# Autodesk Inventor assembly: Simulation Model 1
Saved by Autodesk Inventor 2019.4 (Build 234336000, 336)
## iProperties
Created: 2020-06
Part Number: Simulation Model 1
Document SubType Name: Assembly
Designer: Administrator
Title: Simulation Model 1
Author: Administrator
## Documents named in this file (4)
- c:\worker\convert-fusion-r04\tmp\job-1\14\output\files\60eb285b-71d1-488d-9ab3-3d253d6979d6\d2fabd28-60b9-4d7e-8ef3-2e5a03d44e75.iam
- c:\worker\convert-fusion-r04\tmp\job-1\14\output\files\60eb285b-71d1-488d-9ab3-3d253d6979d6\Component5.ipt
- c:\worker\convert-fusion-r04\tmp\job-1\14\output\files\60eb285b-71d1-488d-9ab3-3d253d6979d6\001 Roller v5.ipt
- c:\worker\convert-fusion-r04\tmp\job-1\14\output\files\60eb285b-71d1-488d-9ab3-3d253d6979d6\Component7.ipt
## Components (3 placed, 3 different names)
1. Component5:1
2. 001 Roller v5:1
3. Component7:1
